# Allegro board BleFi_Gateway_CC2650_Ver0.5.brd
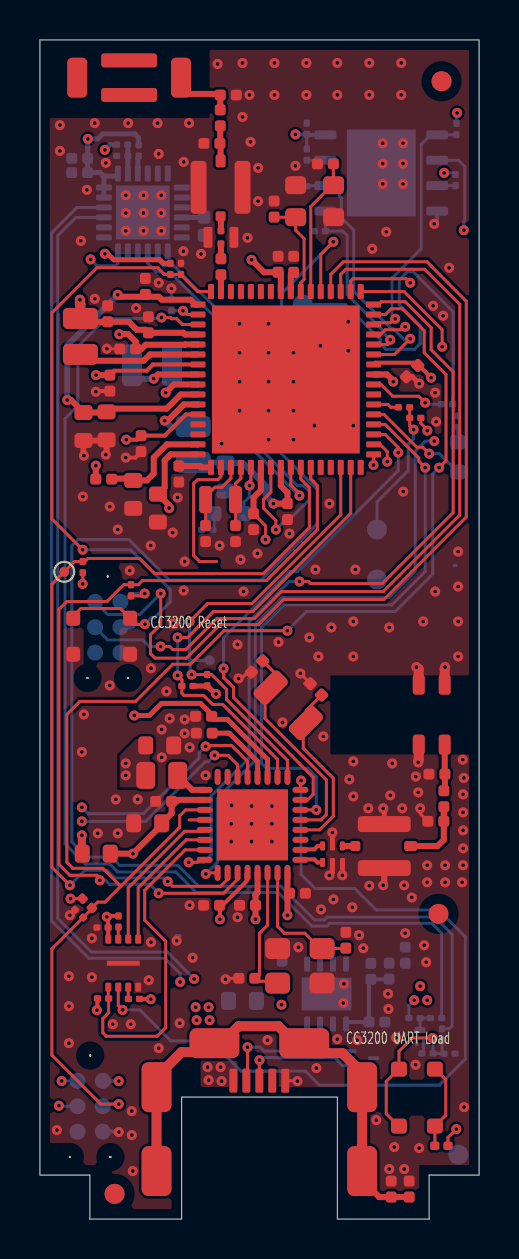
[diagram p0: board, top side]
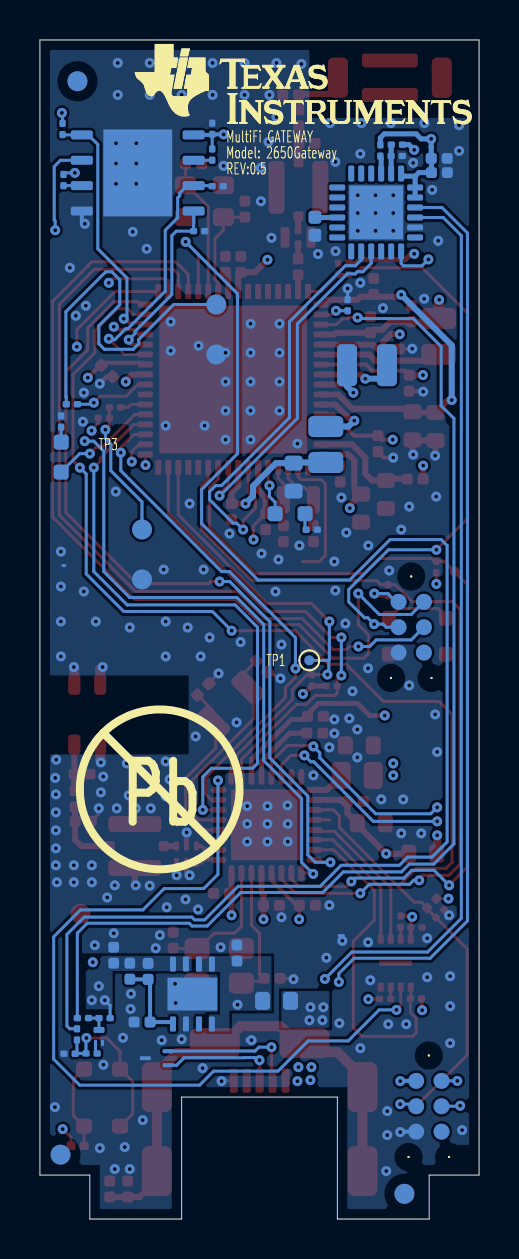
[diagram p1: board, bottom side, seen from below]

Outline 22 x 59 mm; copper layers: TOP, LAYER2, LAYER3, BOTTOM. Coordinates in mm from the lower left corner of the outline.
Outline path: 0,59 0,2.2 2.5,2.2 2.5,0 7.1,0 7.1,6.1 14.9,6.1 14.9,0 19.5,0 19.5,2.2 22,2.2 22,59 0,59

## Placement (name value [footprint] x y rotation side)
A1  ANTENNA_2450AT42B100  [ANTENNA_2450AT42B100N]  7.07 57.11 180 top
A3  2450AT18D0100  [ANTENNA_2450AT18D0100N]  20.28 23.74 90 top
ANT1  1pF  [CAPC1005X60L]  9.03 54.7 90 top
ANT2  22nH  [INDC1005X60L]  8.22 53.82 0 top
ANT3  DNM  [RESC1005X40L]  9.04 56.25 0 top
C15  DNM  [CAPC1005X60L]  20.29 22.26 180 top
C25  DNM  [CAPC1005X60L]  10.77 12.05 180 top
C26  1uF  [CAPC1005X60L]  8.63 24.31 180 top
C27  DNM  [CAPC1005X60L]  15.33 13.55 90 top
C35  100nF  [CAPC0603X35L]  2.16 15.09 135 top
C36  12pF  [CAPC1005X60L]  11.16 27.93 225 top
C38  12pF  [CAPC1005X60L]  14.11 26.22 135 top
C40  DNM  [CAPC1005X60L]  20.23 19.9 180 top
C99  10uF  [CAPC1005X60L]  12.13 12.91 90 bottom
C101  100nF  [CAPC1005X60L]  18.93 42.71 225 top
C111  100nF  [CAPC1005X60L]  8.6 25.16 180 top
C191  100nF  [CAPC1005X60L]  6.6 20.9 180 top
C192  10uF  [CAPC1608X90N]  6.1 19.8 180 top
C221  6.2pF  [CAPC1005X60L]  14.7 52.8 180 top
C231  6.2pF  [CAPC1005X60L]  11.73 50.94 270 top
C241  100nF  [CAPC1005X60L]  12.71 47.38 90 top
C251  100nF  [CAPC1005X60L]  11.93 47.38 90 top
C271  100nF  [CAPC1005X60L]  9 15.7 180 top
C281  100nF  [CAPC1005X60L]  10.8 15.7 180 top
C311  10pF  [CAPC1005X60L]  9.07 47.25 90 top
C321  100nF  [CAPC1005X60L]  12.5 16.3 0 top
C322  100nF  [CAPC0603X35L]  7.07 47.83 270 top
C331  1uF  [CAPC1005X60L]  5.28 46.27 90 top
C361  100nF  [CAPC1005X60L]  5.43 44.35 90 top
C371  4.7uF  [CAPC1005X60N]  4.8 43.54 180 top
C382  100nF  [CAPC1005X60L]  3.39 44.9 90 top
C391  4.7uF  [CAPC1005X60N]  3.5 42.23 270 top
C421  22uF  [CAPC1608X90L]  3.34 40.39 270 top
C422  22uF  [CAPC1608X90L]  2.18 40.36 270 top
C432  10uF  [CAPC1608X90L]  9.29 36.43 90 bottom
C441  4.7uF  [CAPC1005X60N]  5.07 39.2 270 top
C471  10uF  [CAPC1608X90L]  4.67 36.96 270 top
C481  10uF  [CAPC1608X90L]  5.91 36.28 270 top
C491  100nF  [CAPC1005X60L]  6.96 37.68 270 top
C511  22pF  [CAPC1005X60L]  8.3 34.7 270 top
C521  22pF  [CAPC1005X60L]  9.8 34.7 270 top
C541  100nF  [CAPC1005X60L]  10.7 35.3 270 top
C561  100nF  [CAPC1005X60L]  12.4 35.8 270 top
C562  4.7uF  [CAPC1005X60L]  18.5 1.1 90 top
C563  15pF  [CAPC1005X60L]  17.49 12.8 270 bottom
C564  10uF  [CAPC1005X60L]  18.3 12.8 90 bottom
C565  10uF  [CAPC1005X60L]  2.39 52.36 180 bottom
C566  10uF  [CAPC1005X60L]  2.4 53.07 180 bottom
C567  4.7uF  [CAPC1005X60N#2]  8.23 50.13 270 bottom
C568  100nF  [CAPC0603X35L]  13.37 54.27 90 bottom
C574  10uF  [CAPC1608X90N]  5.3 23.7 0 top
C576  100nF  [CAPC0603X35L]  3.42 14.59 180 top
CR1  LS L296-P2Q2-1  [LEDC1708X67L]  20.93 38.88 270 bottom
CR2  LPL296-J2L2-25  [LEDC1707X65L]  8.72 35.29 0 bottom
CR4  DIODE_TPD2EUSB30DR_V1  [SOTFL35P100X50-3M]  15.58 7.7 90 bottom
FIDU8  FIDU_1MM  [FID100X115]  19.97 15.27 0 top
FIDU11  FIDU_1MM  [FID100X115]  3.74 1.26 0 top
FIDU12  FIDU_1MM  [FID100X115]  20.12 56.93 0 top
FIDU13  FIDU_1MM  [FID100X115]  20.97 3.22 180 bottom
FIDU14  FIDU_1MM  [FID100X115]  20.12 56.93 180 bottom
FIDU15  FIDU_1MM  [FID100X115]  3.74 1.26 180 bottom
FL1  DEA202450BT-1294C1  [FIL_DEA202450BT-1294C1N]  9.07 48.8 0 top
FL2  LFB182G  [FIL_LFB182G45BG2D280N]  15.16 18.67 180 top
FL3  BLM18HE152SN1  [FIL_BLM18HE152SN1DL]  3.52 18.28 180 top
J1  MS-156HF  [HIROSE_MS156HFL]  9.05 52.95 270 top
J2  MS-156HF  [HIROSE_MS156HFL]  18.58 18.66 180 top
J3  47491-0001  [MOLEX_474910001L]  9.69 6.92 270 top
L381  2.2uH  [INDC2016X100L]  2.03 43.27 90 top
L401  1uH  [INDC2520X120L]  4.61 42.73 0 bottom
L431  2.2uH  [INDC2016X100L]  7.68 39.66 270 bottom
L474  CIM10U800N  [INDC1608X100L]  9.45 10.92 0 bottom
L475  10uH  [INDC2012X150L]  6.9 22.2 180 top
NOREF  -  []  2.5 0.71 0 top
NOREF#2  -  []  19.5 1.57 0 top
NOREF#3  -  []  18.94 0 90 top
NOREF#4  -  []  4.26 0 90 top
NOREF#5  -  []  0 56.79 0 top
NOREF#6  -  []  0 3.11 0 top
P4  TC2030-CTX-NL  [TAGCONNECT_TC2030-CTX-NLN]  3.15 6.91 270 bottom
P5  TC2030-CTX-NL  [TAGCONNECT_TC2030-CTX-NLN]  4.03 30.88 270 bottom
Q1  CSD13381F4  [DFN100X60X35-3A2N]  19.21 8.81 180 bottom
R10  270  [RESC0603X35L]  20.94 40.19 270 bottom
R12  0  [RESC1005X40L]  20.24 21.43 270 top
R21  270  [RESC0603X35L]  20.68 40.77 180 bottom
R22  270  [RESC0603X35L]  18.52 40.62 180 top
R24  270  [RESC0603X35L]  8.1 34.49 0 bottom
R25  100k  [RESC0603X35L]  12.82 51.68 0 bottom
R26  100k  [RESC0603X35N]  2.6 15.57 135 top
R55  30.1k  [RESC1005X40L]  17.28 9.86 180 bottom
R56  51k  [RESC1005X40L]  16.58 11.99 90 bottom
R61  10k  [RESC0603X35L]  18.52 40.09 0 top
R321  10k  [RESC0603X35L]  6.53 47.26 90 top
R329  10k  [RESC0603X35L]  4.56 31.74 270 top
R330  10k  [RESC0603X35L]  2.15 32.9 270 top
R331  10k  [RESC0603X35L]  8.38 27.24 270 top
R332  10k  [RESC0603X35L]  7.11 26.67 0 top
R333  1Meg  [RESC1005X40L]  17.6 1.9 270 top
R337  270  [RESC0603X35L]  3.84 53.76 0 bottom
R338  270  [RESC0603X35L]  4.41 53.2 180 bottom
R339  4.7k  [RESC0603X35L]  4.95 53.75 270 bottom
R341  100k  [RESC0603X35L]  6.58 46.01 270 bottom
R472  0  [RESC1005X40L]  2.8 37.03 0 top
R532  10k  [RESC0603X35L]  13.37 52.98 90 bottom
R533  10k  [RESC0603X35L]  20.82 51.71 90 bottom
R534  10k  [RESC0603X35L]  13.74 49.43 0 bottom
R535  100k  [RESC0603X35L]  20.87 54.27 90 bottom
R537  10k  [RESC0603X35L]  3.94 14.61 90 top
R538  10k  [RESC0603X35L]  4.43 11.01 0 top
R541  100k  [RESC0603X35L]  3.44 11.04 180 top
R548  10k  [RESC0603X35L]  19.04 10.05 180 bottom
R549  2.7k  [RESC0603X35L]  20.8 8.27 180 bottom
R550  0  [RESC0603X35AN]  20.13 10.06 180 bottom
R551  0  [RESC0603X35AN]  20.14 8.96 90 bottom
R552  0  [RESC0603X35AN]  19.69 8.28 180 bottom
R553  100  [RESC0603X35N]  19.78 3.66 0 top
SW1  BUTTON_CARBON  [SWITCH_TEXAS]  13.17 45.76 90 bottom
SW2  BUTTON_CARBON  [SWITCH_TEXAS]  16.89 34.5 90 bottom
SW3  TL3700AF160Q  [SW_TL3700AF160Q_A2N]  19.79 4.65 90 top
SW4  TL3700AF160Q  [SW_TL3700AF160Q_A2L]  1.67 28.26 0 top
TP1  20_SMD  [TP50]  8.51 27.96 180 bottom
TP2  20_SMD  [TP50]  1.22 32.39 0 top
U1  CC3200R1M2RGC  [QFNFC50P900X900X100-65FL]  16.72 38.26 90 top
U2  CC26xx-5x5  [QFNFC50P500X500X100-33AL]  13.05 17.97 90 top
U3  W25X80ALZPIG  [SON127P600X500X80-9N]  19.9 54.25 270 bottom
U4  W25X20CLUXIG  [SON50P300X200X60-9L]  3.42 11.6 0 top
U5  IC_PERIPH_CP2105_QFN24_V1  [QFNFC50P400X400X80-25BM]  3.2 49.12 90 bottom
U7  TPS79601DR  [SON65P300X300X100-9AL]  13.39 12.76 0 bottom
UNK#REFDES  -  []  16.25 58.8 180 bottom
UNK#REFDES#2  -  [unnamed#2]  20 17.5 180 bottom
Y1  32.768kHz  [XTAL_FC-135L]  13.33 24.82 135 top
Y2  24MHz  [OSCCC250X320X60-4L]  14.14 13.54 180 top
Y3  40MHz  [OSCCC200X250X90-4AL]  12.81 50.13 0 top
Y4  32.768kHz  [XTAL_FC12ML]  9.8 36 180 top

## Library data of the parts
A1 = ANTENNA_2450AT42B100
A3 = ANTENNA_CERAMIC_1_3_GND: User Part Number: #PN; alternate symbols: (ANTENNA_2450AT18D0100L,ANTENNA_2450AT18D0100M)
ANT1 C15 C25-C27 C36 C38 C40 C99 C101 C111 C191 C221 C231 C241 C251 C271 C281 C311 C321 C331 C361 C371 C382 C391 C441 C491 C511 C521 C541 C561-C566 = CAPACITOR: alternate symbols: (CAPC1005X60L,CAPC1005X60M)
ANT2 = INDUCTOR: alternate symbols: (INDC1005X60M,INDC1005X60L)
ANT3 R55 R56 R333 R472 = RESISTOR: alternate symbols: (RESC1005X40L,RESC1005X40M)
C35 C322 C568 C576 = CAPACITOR: alternate symbols: (CAPC0603X35L,CAPC0603X35M)
C192 C421 C422 C432 C471 C481 C574 = CAPACITOR: alternate symbols: (CAPC1608X90L,CAPC1608X90M)
C567 = CAPACITOR: User Part Number: #PN; alternate symbols: (CAPC1005X60L,CAPC1005X60M)
CR1 = LED: alternate symbols: (LEDC1708X67L,LEDC1708X67M)
CR2 = LED: alternate symbols: (LEDC1707X65L,LEDC1707X65M)
CR4 = DIODE_TPD2EUSB30DR_V1: User Part Number: #PN
FIDU8 FIDU11-FIDU15 = FIDMARK
FL1 = FILTER_BPF: User Part Number: #PN
FL2 = FILTER_LFB_0: alternate symbols: (FIL_LFB182G45BG2D280L,FIL_LFB182G45BG2D280M)
FL3 = FILTER_2PIN: alternate symbols: (FIL_BLM18HE152SN1DL,FIL_BLM18HE152SN1DM)
J1 = CONN_COAX_MS-156HF: alternate symbols: (HIROSE_MS156HFAL,HIROSE_MS156HFAM,HIROSE_MS156HFL,HIROSE_MS156HFM)
J2 = CONN_COAX_MS-156HF: alternate symbols: (HIROSE_MS156HFL,HIROSE_MS156HFM)
J3 = CONN_USB_MICRO_5+6_S: User Part Number: #PN; alternate symbols: (MOLEX_474910001L,MOLEX_474910001M)
L381 L431 = INDUCTOR: User Part Number: #PN; alternate symbols: (INDC2016X100L,INDC2016X100M)
L401 = INDUCTOR: alternate symbols: (INDC2520X120L,INDC2520X120M)
L474 = INDUCTOR: alternate symbols: (INDC1608X100L,INDC1608X100M)
L475 = INDUCTOR: alternate symbols: (INDC2012X150L,INDC2012X150M)
P4 P5 = CONN_IDC_TC2030-CTX-NL: alternate symbols: (TAGCONNECT_TC2030-CTX-NLL,TAGCONNECT_TC2030-CTX-NLM)
Q1 = MOSFET_N_CSD13381F4: User Part Number: #PN
R10 R21 R22 R24-R26 R61 R321 R329-R332 R337-R339 R341 R532-R535 R537 R538 R541 R548 R549 R553 = RESISTOR: alternate symbols: (RESC0603X35L,RESC0603X35M)
R12 = RESISTOR_HOR: alternate symbols: (RESC1005X40L,RESC1005X40M)
R550-R552 = RESISTOR: alternate symbols: (RESC0603X35AL,RESC0603X35AM)
SW1 SW2 = BUTTON_CARBON_2
SW3 SW4 = SWITCH_TACT_V1: User Part Number: #PN; alternate symbols: (SW_TL3700AF160Q_A2L,SW_TL3700AF160Q_A2M)
TP1 TP2 = TEST_POINT
U1 = IC_PROC_CC3200_VQFN64: User Part Number: #PN; alternate symbols: (QFNFC50P900X900X100-65FL,QFNFC50P900X900X100-65FM)
U2 = IC_RF_CC26XX_5x5_QFN32: alternate symbols: (QFNFC50P500X500X100-33AL,QFNFC50P500X500X100-33AM)
U3 = IC_FLASH_W25X80AL_WSON8: alternate symbols: (SON127P600X500X80-9L,SON127P600X500X80-9M)
U4 = IC_FLASH_W25X20CL_USON8: alternate symbols: (SON50P300X200X60-9L,SON50P300X200X60-9M)
U5 = IC_PERIPH_CP2105_QFN24_V1_0
U7 = IC_PM_TPS79601_SON8: alternate symbols: (SON65P300X300X100-9AL,SON65P300X300X100-9AM)
Y1 = CRYSTAL: alternate symbols: (XTAL_FC-135L,XTAL_FC-135M)
Y2 = XTAL_4PIN_S: alternate symbols: (OSCCC250X320X60-4L,OSCCC250X320X60-4M)
Y3 = CRYSTAL_13: alternate symbols: (OSCCC200X250X90-4AL,OSCCC200X250X90-4AM)
Y4 = XTAL: alternate symbols: (XTAL_FC12ML,XTAL_FC12MM)

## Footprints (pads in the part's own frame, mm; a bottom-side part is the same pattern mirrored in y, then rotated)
ANTENNA_2450AT18D0100N
  custom 0.15x0.15 smd: 1(0,0) 2(3,0) 3(3,1.3) 4(0,1.3)
ANTENNA_2450AT42B100N
  custom 0.25x0.25 smd: 1(0,0) 2(5.2,0)
  custom 0.175x0.175 smd: 3(2.6,-0.865) 4(2.6,0.865)
CAPC0603X35L
  custom 0.08x0.08 smd: 1(0,0) 2(0.56,0)
CAPC1005X60L
  custom 0.135x0.135 smd: 1(0,0) 2(0.8,0)
CAPC1005X60N
  custom 0.135x0.135 smd: 1(0,0) 2(0.8,0)
CAPC1005X60N#2
  custom 0.16x0.16 smd: 1(0,0) 2(0.9,0)
CAPC1608X90L
  custom 0.187x0.187 smd: 1(0,0) 2(1.4,0)
CAPC1608X90N
  custom 0.187x0.187 smd: 1(0,0) 2(1.4,0)
DFN100X60X35-3A2N
  custom 0.037x0.037 smd: 1(0,0) 2(0.35,0)
  custom 0.075x0.075 smd: 3(0.175,0.65)
FID100X115
  round 1 smd: 1(0,0)
FIL_BLM18HE152SN1DL
  custom 0.187x0.187 smd: 1(0,0) 2(1.4,0)
FIL_DEA202450BT-1294C1N
  custom 0.088x0.088 smd: 1(0,0) 3(0,0.65)
  custom 0.113x0.113 smd: 2(-0.65,0.325) 4(0.65,0.325)
FIL_LFB182G45BG2D280N
  custom 0.062x0.062 smd: 1(0,0) 2(0.5,0) 3(1,0) 4(1,0.825) 5(0.5,0.825) 6(0,0.825)
HIROSE_MS156HFL
  custom 0.125x0.125 smd: 1(0,0) 2(2.775,0)
  custom 0.2x0.2 smd: 3(1.325,-1.1) 4(1.325,1.1)
INDC1005X60L
  custom 0.135x0.135 smd: 1(0,0) 2(0.8,0)
INDC1608X100L
  custom 0.187x0.187 smd: 1(0,0) 2(1.4,0)
INDC2012X150L
  custom 0.237x0.237 smd: 1(0,0) 2(1.6,0)
INDC2016X100L
  custom 0.263x0.263 smd: 1(0,0) 2(1.8,0)
INDC2520X120L
  custom 0.25x0.25 smd: 1(0,0) 2(2,0)
LEDC1707X65L
  custom 0.187x0.187 smd: 1(0,0) 2(1.5,0)
LEDC1708X67L
  custom 0.187x0.187 smd: 1(0,0) 2(1.5,0)
MOLEX_474910001L
  custom 0.1x0.1 smd: 1(0,0) 2(0,0.65) 3(0,1.3) 4(0,1.95) 5(0,2.6)
  custom 0.375x0.375 smd: 6(4.525,-3.85) 7(0.325,-3.85) 8(-1.875,-0.95) 9(-1.875,3.55) 10(0.325,6.45) 11(4.525,6.45)
OSCCC200X250X90-4AL
  custom 0.225x0.225 smd: 1(0,0) 2(1.9,0) 3(1.9,1.6) 4(0,1.6)
OSCCC250X320X60-4L
  custom 0.263x0.263 smd: 1(0,0) 2(2.23,0) 3(2.23,1.73) 4(0,1.73)
QFNFC50P400X400X80-25BM
  custom 0.075x0.075 smd: 1(0,0) 2(0.5,0) 3(1,0) 4(1.5,0) 5(2,0) 6(2.5,0) 7(3.2,0.7) 8(3.2,1.2) 9(3.2,1.7) 10(3.2,2.2) 11(3.2,2.7) 12(3.2,3.2) 13(2.5,3.9) 14(2,3.9) 15(1.5,3.9) 16(1,3.9) 17(0.5,3.9) 18(0,3.9) 19(-0.7,3.2) 20(-0.7,2.7) 21(-0.7,2.2) 22(-0.7,1.7) 23(-0.7,1.2) 24(-0.7,0.7)
  rect 2.7x2.7 smd: 25(1.25,1.95)
QFNFC50P500X500X100-33AL
  oval 0.3x0.8 smd: 1(0,0) 2(0.5,0) 3(1,0) 4(1.5,0) 5(2,0) 6(2.5,0) 7(3,0) 8(3.5,0) 17(3.5,4.8) 18(3,4.8) 19(2.5,4.8) 20(2,4.8) 21(1.5,4.8) 22(1,4.8) 23(0.5,4.8) 24(0,4.8)
  oval 0.8x0.3 smd: 9(4.15,0.65) 10(4.15,1.15) 11(4.15,1.65) 12(4.15,2.15) 13(4.15,2.65) 14(4.15,3.15) 15(4.15,3.65) 16(4.15,4.15) 25(-0.65,4.15) 26(-0.65,3.65) 27(-0.65,3.15) 28(-0.65,2.65) 29(-0.65,2.15) 30(-0.65,1.65) 31(-0.65,1.15) 32(-0.65,0.65)
  rect 3.55x3.55 smd: 33(1.75,2.4)
QFNFC50P900X900X100-65FL
  custom 0.075x0.075 smd: 1(0,0) 2(0.5,0) 3(1,0) 4(1.5,0) 5(2,0) 6(2.5,0) 7(3,0) 8(3.5,0) 9(4,0) 10(4.5,0) 11(5,0) 12(5.5,0) 13(6,0) 14(6.5,0) 15(7,0) 16(7.5,0) 17(8.15,0.65) 18(8.15,1.15) 19(8.15,1.65) 20(8.15,2.15) 21(8.15,2.65) 22(8.15,3.15) 23(8.15,3.65) 24(8.15,4.15) 25(8.15,4.65) 26(8.15,5.15) 27(8.15,5.65) 28(8.15,6.15) 29(8.15,6.65) 30(8.15,7.15) 31(8.15,7.65) 32(8.15,8.15) 33(7.5,8.8) 34(7,8.8) 35(6.5,8.8) 36(6,8.8) 37(5.5,8.8) 38(5,8.8) 39(4.5,8.8) 40(4,8.8) 41(3.5,8.8) 42(3,8.8) 43(2.5,8.8) 44(2,8.8) 45(1.5,8.8) 46(1,8.8) 47(0.5,8.8) 48(0,8.8) 49(-0.65,8.15) 50(-0.65,7.65) 51(-0.65,7.15) 52(-0.65,6.65) 53(-0.65,6.15) 54(-0.65,5.65) 55(-0.65,5.15) 56(-0.65,4.65) 57(-0.65,4.15) 58(-0.65,3.65) 59(-0.65,3.15) 60(-0.65,2.65) 61(-0.65,2.15) 62(-0.65,1.65) 63(-0.65,1.15) 64(-0.65,0.65)
  rect 7.4x7.4 smd: 65(3.75,4.4)
RESC0603X35AN
  custom 0.08x0.08 smd: 1(0,0) 2(0.56,0)
RESC0603X35L
  custom 0.08x0.08 smd: 1(0,0) 2(0.56,0)
RESC0603X35N
  custom 0.105x0.105 smd: 1(0,0) 2(0.66,0)
RESC1005X40L
  custom 0.135x0.135 smd: 1(0,0) 2(0.8,0)
SON50P300X200X60-9L
  custom 0.075x0.075 smd: 1(0,0) 2(0.5,0) 3(1,0) 4(1.5,0) 5(1.5,2.4) 6(1,2.4) 7(0.5,2.4) 8(0,2.4)
  rect 1.651x0.249 smd: 9(0.75,1.2)
SON65P300X300X100-9AL
  custom 0.075x0.075 smd: 1(0,0) 2(0.65,0) 3(1.3,0) 4(1.95,0) 5(1.95,3) 6(1.3,3) 7(0.65,3) 8(0,3)
  rect 2.5x1.65 smd: 9(0.975,1.5)
SON127P600X500X80-9N
  custom 0.113x0.113 smd: 1(0,0) 2(1.27,0) 3(2.54,0) 4(3.81,0) 5(3.81,5.6) 6(2.54,5.6) 7(1.27,5.6) 8(0,5.6)
  rect 4.35x3.45 smd: 9(1.905,2.8)
SOTFL35P100X50-3M
  custom 0.05x0.05 smd: 1(0,0) 2(0.7,0) 3(0.35,1.14)
SW_TL3700AF160Q_A2L
  custom 0.175x0.175 smd: 1(0,0) 2(2.85,0) 3(0,1.8) 4(2.85,1.8)
SW_TL3700AF160Q_A2N
  custom 0.187x0.187 smd: 1(0,0) 2(2.85,0) 3(0,1.8) 4(2.85,1.8)
SWITCH_TEXAS
  round 1 smd: 1(0,0) 2(-2.5,0)
TAGCONNECT_TC2030-CTX-NLN
  round 0.1 hole 1 unplated: (-1.27,0.635) (3.81,-0.381) (3.81,1.651)
  round 0.8 smd: 1(0,0) 2(0,1.27) 3(1.27,0) 4(1.27,1.27) 5(2.54,0) 6(2.54,1.27)
TP50
  round 0.5 smd: 1(0,0)
unnamed#2
  oval 0.025x0.051 smd: 1(4,4)
XTAL_FC12ML
  custom 0.163x0.163 smd: 1(0,0) 2(1.5,0)
XTAL_FC-135L
  custom 0.237x0.237 smd: 1(0,0) 2(2.5,0)

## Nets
GND: A3.2(GND#2) A3.3(GND#3) A3.4(GND#4) ANT2.1 ANT3.2 C15.2 C25.2 C26.2 C27.2 C35.2 C36.2 C38.2 C40.2 C99.2 C101.2 C111.2 C191.2 C192.2 C221.2 C231.1 C241.2 C251.2 C271.2 C281.2 C321.2 C322.1 C331.2 C361.2 C371.2 C382.2 C391.2 C421.2 C422.2 C432.1 C441.2 C471.2 C481.2 C491.2 C511.2 C521.2 C541.2 C561.2 C562.2 C564.2 C565.2 C566.2 C567.2 C568.2 C574.2 C576.2 CR4.3(GND) FL1.2(GND#2) FL1.4(GND#4) FL2.2(GND) FL2.5(GND#5) FL2.6(GND#6) J1.3 J1.4 J2.3 J2.4 J3.5(GND#5) P4.5(GND) P5.5(GND) Q1.2(S) R10.1 R24.1 R25.1 R55.1 R333.1 R338.2 R341.1 R534.1 R549.1 SW1.2 SW2.2 SW4.1 SW4.2 U1.65(EGP) U2.33(VSS) U3.4(GND) U3.9(EGP) U4.4(GND) U4.9(EGP) U5.2(GND) U5.25(EGP) U7.6(GND) U7.9(GND/TAB) Y2.2 Y2.4 Y3.2 Y3.4
VDD: C101.1 C371.1 C391.1 C441.1 C541.1 C563.1 C564.1 C565.1 C566.1 C568.1 C576.1 FL3.2 P4.1(VDD) P5.1(VDD) R26.2 R56.2 R61.2 R321.2 R329.2 R330.2 R331.2 R332.2 R339.1 R472.1 R532.2 R533.2 R535.2 R537.2 R538.2 R541.2 R548.2 R553.2 U1.10(VIN_IO1) U1.37(VIN_DCDC_ANA) U1.39(VIN_DCDC_PA) U1.44(VIN_DCDC_DIG) U1.54(VIN_IO2) U3.8(VCC) U4.8(VCC) U5.5(VIO) U5.6(VDD) U5.7(REGIN) U7.3(OUT#3) U7.4(OUT#4)
VDD_IN: C99.1 L474.2 R337.1 U7.1(IN#1) U7.2(IN#2) U7.8(EN)
VDDR: C281.1 C321.1 C574.1 L475.2 U2.29(VDDR#29) U2.32(VDDR#32)
VDDS: C111.1 C191.1 C192.1 C271.1 FL3.1 U2.11(VDDS2) U2.18(VDDS_DCDC) U2.28(VDDS)
CC2650 BUTTON: R21.2 U1.8(GPIO_17)
CC2650 JTAG_TCK: P4.4(TCK) U2.14(JTAG_TCKC)
CC2650 JTAG_TMS: P4.2(TMS) U2.13(JTAG_TMSC)
CC2650 LED: CR2.2(A) U1.53(GPIO_30)
CC2650 MISO: U2.8(DIO_2) U4.2(DO/IO1)
CC2650 MOSI: U2.22(DIO_9) U4.5(DI/IO0)
CC2650 SCLK: U2.21(DIO_8) U4.6(CLK)
CC3200 BUTTON: R22.2 U1.6(GPIO_15)
CC3200 JTAG_TCK: P5.4(TCK) U1.19(TCK)
CC3200 JTAG_TMS: P5.2(TMS) U1.20(TMS)
CC3200 LED: CR1.2(A) U1.5(GPIO_14)
COEX0: U1.16(TDI) U2.24(DIO_11)
COEX1: U1.17(TDO) U2.25(DIO_12)
COEX2: R330.1 TP2.1 U1.58(GPIO_3) U2.26(DIO_13)
COEX3: R329.1 U1.59(GPIO_4) U2.27(DIO_14)
D+: CR4.1(D+) J3.3(D+) U5.3(D+)
D-: CR4.2(D-) J3.2(D-) U5.4(D-)
DCDC_SW: L475.1 U2.17(DCDC_SW)
FLASH CS: R541.1 U2.23(DIO_10) U4.1(NCS)
HS1: R331.1 TP1.1 U1.62(GPIO_7) U2.9(DIO_3)
HS2: R332.1 U1.63(GPIO_8) U2.10(DIO_4)
I2C SCL: U1.1(GPIO_10)
I2C SDA: U1.2(GPIO_11)
NRESET CC2650: C35.1 P4.3(NRST) R26.1 U1.15(GPIO_22) U2.19(RESET_N)
NRESET CC3200: C322.2 P5.3(NRST) R321.1 SW4.3 SW4.4 U1.32(NRESET)
SOP0: R550.1 U1.35(SOP0)
SOP2: R551.2 U1.21(SOP2)
SSPI_CLK: R25.2 U1.11(FLASH_SPI_CLK) U3.6(CLK)
SSPI_CS: R535.1 U1.14(FLASH_SPI_CS) U3.1(NCS)
SSPI_MISO: U1.13(FLASH_SPI_DIN) U3.2(DO)
SSPI_MOSI: R534.2 U1.12(FLASH_SPI_DOUT) U3.5(DIO)
U16 RESET: U1.18(GPIO_28)
UART RX: U1.4(GPIO_13) U2.6(DIO_0)
UART TX: U1.3(GPIO_12) U2.7(DIO_1)
UARTFL RX: U1.57(GPIO_2) U5.21(TXD_SCI)
UARTFL TX: U1.55(GPIO_1) U5.20(RXD_SCI)
N618375: CR1.1(C) R10.2
N618511: R21.1 SW1.1
N618515: R22.1 R61.1 SW2.1
N622814: CR2.1(C) R24.2
N631122: A3.1(FEEDING POINT) C15.1 R12.1
N631156: C40.1 J2.1 R12.2
N631258: C38.1 U2.4(X32K_Q1) Y1.1
N631262: C36.1 U2.5(X32K_Q2) Y1.2
N632758: FL2.4(BP2) U2.1(RF_P)
N632762: FL2.1(UBP) J2.2
N632770: FL2.3(BP1) U2.2(RF_N)
N632870: C26.1 U2.12(DCOUPL)
N632938: C27.1 U2.31(X24M_P) Y2.1
N632966: C25.1 U2.30(X24M_N) Y2.3
N638264: R549.2 R551.1 R552.1 SW3.3 SW3.4
N638912: C563.2 R55.2 R56.1 U7.5(FB)
N639461: C562.1 J3.6(GND#6) J3.7(GND#7) J3.8(GND#8) J3.9(GND#9) J3.10(GND#10) J3.11(GND#11) R333.2
N742795: R337.2 R338.1 U5.8(VBUS)
N744104: R339.2 U5.9(NRST)
N744832: C567.1 U5.16(NC/DCD_ECI/VPP)
N759449: C471.1 R472.2 U1.47(VDD_ANA2)
N759557: C251.1 C361.1 C382.1 C481.1 L381.2 U1.25(LDO_IN2) U1.36(LDO_IN1) U1.48(VDD_ANA1)
N759727: C331.1 C421.1 C422.1 U1.33(VDD_PA_IN) U1.42(DCDC_PA_OUT)
N759853: C311.1 U1.31(RF_BG)
N759877: C231.2 U1.23(WLAN_XTAL_P) Y3.1
N759881: C221.1 U1.22(WLAN_XTAL_N) Y3.3
N759929: C521.1 U1.52(RTC_XTAL_N) Y4.1
N760199: C511.1 U1.51(RTC_XTAL_P) Y4.2
N760665: R341.2 U1.34(SOP1)
N760769: L401.1 U1.40(DCDC_PA_SW_P)
N760773: L401.2 U1.41(DCDC_PA_SW_N)
N760777: C241.1 U1.24(VDD_PLL)
N760781: C491.1 U1.49(VDD_RAM)
N760789: L431.1 U1.43(DCDC_DIG_SW)
N760837: C432.2 C561.1 L431.2 U1.9(VDD_DIG1) U1.56(VDD_DIG2)
N761005: L381.1 U1.38(DCDC_ANA_SW)
N761145: A1.1(FEED POINT) ANT1.2 ANT3.1
N761299: C311.2 FL1.1(IN)
N761303: FL1.3(OUT) J1.2
N761307: ANT1.1 ANT2.2 J1.1
N764692: R532.1 U3.7(NHOLD)
N764700: R533.1 U3.3(NWP)
N804286: J3.1(VBUS) L474.1
N881760: R537.1 U4.7(NHOLD)
N881768: R538.1 U4.3(NWP)
N913675: R553.1 SW3.1 SW3.2
N916681: Q1.3(D) R548.1 R550.2
N924850: Q1.1(G) R552.2

Pads without a net: A1 2 3 4; FIDU8 1; FIDU11 1; FIDU12 1; FIDU13 1; FIDU14 1; FIDU15 1; J3 4; P4 6; P5 6; U1 7 26 27 28 29 30 45 46 50 60 61 64; U2 3 15 16 20; U5 1 10 11 12 13 14 15 17 18 19 22 23 24; U7 7; UNK#REFDES#2 1

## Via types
v1: diameter 0.5, hole 0.2, TOP to BOTTOM, 334 vias

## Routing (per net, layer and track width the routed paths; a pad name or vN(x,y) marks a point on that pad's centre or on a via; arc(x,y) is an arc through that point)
GND: length 19.1
  TOP w0.15: 13.98,15.47 13.99,15.49 v1(14.08,15.49) ; 7.25,32.85 v1(7.25,32.9) ; 7.04,36.1 v1(6.9,36.1) ; C25.2 9.4,12.05 9.35,12 v1(9.3,12) ; v1(9.95,27.05) 10.1,27.05 10.3,27.25 10.48,27.25 C36.2 ; v1(12.9,6.9) 12.77,6.9 12.75,6.92 J3.5 ; v1(13.05,27.3) 13.55,26.8 13.55,26.79 ; 13.55,26.79 C38.2 13.55,26.79 ; 13.55,26.79 13.26,26.79 ; C371.2 3.36,43.54 v1(3.35,43.55) ; 15.84,14.35 v1(15.99,14.2) ; C40.2 19.05,20.29 v1(19.05,20.55)
  TOP w0.2: v1(4.3,38.1) 4.78,38.1 4.98,38.3 C441.2 ; C391.2 2.83,41.43 v1(2.8,41.4)
  TOP w0.25: FL2.2 14.66,19.33 v1(14.65,19.34) ; v1(15.15,17.2) 15.16,17.21 FL2.6 ; v1(19,41.8) 18.65,42.15 18.36,42.15 ; FL2.5 14.66,17.36 v1(14.5,17.2) ; v1(17.2,20.55) 17.25,20.5 J2.3
  TOP w0.3: v1(17.2,16.7) 17.25,16.75 J2.4 ; v1(2.2,38.2) 2.18,38.22 C422.2 3.31,38.96 C421.2 3.34,38.29 v1(3.3,38.25) ; 6.12,34.87 C481.2 ; v1(6.9,36.1) 6.96,36.16
  TOP w0.5: 18.95,27.55 18.98,27.52 A3.3 ; 20.3,27.55 20.28,27.53 A3.2 ; 18.95,22.95 18.98,22.98 A3.4
  BOTTOM w0.15: R341.1 v1(6.58,46.57) ; 20.85,32.7 20.75,32.7 ; 7.02,14.18 6.8,14.18
  BOTTOM w0.2: v1(3.95,4.35) 3.88,4.35 3.85,4.37 P4.5 ; U3.4 19.9,49.95 v1(19.75,49.8)
  BOTTOM w0.3: 11.55,8.95 v1(11.4,8.95)
  vias: v1(0.85,4.45) v1(1,54.74) v1(1,53.45) v1(1.5,15.2) v1(1.45,12.15) v1(1.45,10.65) v1(1.45,8.8) v1(2.05,48.95) v1(2.1,23.38) v1(2.15,36.15) v1(2.2,25.25) v1(2.35,51.5) v1(2.6,14.05) v1(2.6,12.1) v1(2.74,54.84) v1(2.75,46.05) v1(2.9,19.3) v1(3.3,52.85) v1(3.5,35.65) v1(3.5,26.7) v1(3.65,9.75) v1(3.8,21) v1(3.9,34.5) v1(3.9,19.3) v1(4.3,51.23) v1(4.3,50.34) v1(4.3,49.45) v1(4.42,54.84) v1(4.5,32.45) v1(4.55,9.75) v1(4.6,5.4) v1(4.6,4.2) v1(4.65,2.4) v1(4.82,45.58) v1(4.9,21) v1(5.19,51.23) v1(5.19,50.34) v1(5.19,49.45) v1(5.55,33.7) v1(5.45,11.95) v1(5.56,27.56) v1(5.56,13.85) v1(5.89,54.84) v1(5.95,53.3) v1(5.95,46.85) v1(5.95,8.55) v1(6.08,51.23) v1(6.08,50.34) v1(6.08,49.45) v1(6.1,24.5) v1(6.1,23.1) v1(6.34,26.41) v1(6.5,25.05) v1(6.65,34.35) v1(6.7,29.8) v1(6.85,13.93) v1(7,9.8) v1(7.2,52.9) v1(7.19,48.43) v1(7.2,31.45) v1(7.25,25) v1(7.25,24.3) v1(7.47,54.84) v1(7.5,23.6) v1(7.5,15.7) v1(7.65,13.07) v1(8.07,48.29) v1(8.3,22.2) v1(8.9,57.8) v1(9,33.7) v1(9.1,38.8) v1(9.6,20.7) v1(9.59,19.77) v1(9.59,18.88) v1(9.9,28.75) v1(9.9,15.1) v1(10,44.8) v1(10,43.35) v1(10,41.9) v1(10,40.45) v1(10.05,33) v1(10.15,57.85) v1(10.15,55.15) v1(10.2,31.4) v1(10.4,49.1) v1(10.5,56.25) v1(10.55,53.9) v1(10.6,20.66) v1(10.6,19.77) v1(10.6,18.88) v1(10.93,52.6) v1(10.93,50.93) v1(10.9,33.3) v1(11.45,44.8) v1(11.45,43.35) v1(11.45,41.9) v1(11.45,40.45) v1(11.45,39) v1(11.62,20.66) v1(11.62,19.77) v1(11.62,18.88) v1(11.75,57.85) v1(11.75,56.25) v1(11.95,28.87) v1(12.15,24.85) v1(12.5,34.3) v1(12.7,43.35) v1(12.7,41.9) v1(12.7,40.45) v1(12.7,39) v1(12.8,52.7) v1(12.95,13.6) v1(13.35,57.85) v1(13.35,56.25) v1(13.5,29.1) v1(13.75,39.7) v1(13.8,32.5) v1(13.95,28.15) v1(13.85,7.55) v1(14.05,43.7) v1(14.2,24.15) v1(14.5,35.8) v1(14.6,29.6) v1(14.71,15.99) v1(14.9,57.85) v1(14.9,56.25) v1(14.9,9) v1(15.23,11.77) v1(15.2,10.81) v1(15.45,44.9) v1(15.45,43.45) v1(15.5,22) v1(15.65,15.6) v1(15.7,39.7) v1(15.7,29.9) v1(15.7,28.15) v1(15.7,22.9) v1(15.7,21.15) v1(15.8,32.5) v1(15.9,8.95) v1(16.2,13.55) v1(16.5,57.85) v1(16.5,56.25) v1(16.45,20.55) v1(16.5,16.68) v1(16.65,48.55) v1(16.85,4.95) v1(17.17,53.83) v1(17.17,52.82) v1(17.17,51.8) v1(17.35,49.4) v1(17.44,11.27) v1(17.5,29.6) v1(17.55,21.2) v1(17.46,10.51) v1(17.5,2.5) v1(17.65,22.8) v1(17.84,9.07) v1(17.75,3.6) v1(18.1,57.85) v1(18.1,56.25) v1(18.19,53.83) v1(18.19,52.82) v1(18.19,51.8) v1(18.2,36.4) v1(18.15,20.55) v1(18.25,16.7) v1(18.25,2.5) v1(18.3,14.3) v1(18.63,16.09) v1(18.83,22.14) v1(18.82,7.72) v1(18.86,27.62) v1(18.95,22.85) v1(18.95,21.35) v1(19,3.55) v1(19.2,29.9) v1(19.25,13.7) v1(19.35,12.85) v1(19.4,17.7) v1(19.4,16.85) v1(19.7,45.7) v1(19.8,41.35) v1(19.8,31.4) v1(19.85,39.9) v1(20.2,45.2) v1(20.3,27.62) v1(20.3,17.7) v1(20.3,16.85) v1(20.5,47.6) v1(20.95,33.4) v1(20.95,31.65) v1(20.95,29.9) v1(20.95,28.15) v1(21.18,22.99) v1(21.23,22.07) v1(21.2,21.25) v1(21.2,20.35) v1(21.2,19.45) v1(21.2,18.55) v1(21.2,17.7) v1(21.15,16.85) v1(21.25,5.6)
VDD: length 48.9
  TOP w0.15: R541.2 2.88,10.48 ; R329.2 5.13,31.18 v1(5.25,31.3) ; C541.1 10.7,35.3 11.3,34.69 v1(11.3,34) ; v1(20.86,4.5) 20.44,4.08 R553.2 ; v1(19.41,39.45) 19.41,39.49 19.08,39.82 R61.2 ; v1(2.14,31.78) 2.15,31.79 R330.2 ; R26.2 v1(1.53,16.03)
  TOP w0.2: U1.44 7.31,40.26 6.25,39.2 C441.1 4.87,39 v1(4.33,39) ; U4.8 3.42,14.58 C576.1 3.42,15.06 v1(3.35,15.12) 3.39,15.17 R537.2 ; R538.2 5.54,11.01 v1(5.55,11) ; U1.39 5.66,42.76 5.35,42.45 3.72,42.45 C391.1 ; U1.10 16.81,42.85 18.79,42.85 C101.1 18.94,42.76 v1(19.6,42.1) ; R541.2 2.88,10.48 v1(2.85,10.45)
  TOP w0.25: v1(8.82,26.28) 8.79,26.28 R331.2 8.37,26.67 R332.2 ; R321.2 6.18,47.82 6,48 3.7,48 3.4,48.3 v1(3.25,48.3)
  TOP w0.3: v1(2.8,37.7) 2.8,37.7 R472.1 ; U1.37 7.27,43.76 7.26,43.75 5.3,43.75 5.09,43.54 C371.1 4.8,43.9 4.41,44.29 3.99,44.29 v1(3.98,44.27) ; C541.1 10.7,36.1 11.07,36.47 U1.54 ; C391.1 v1(2.81,42.23)
  TOP w0.4: v1(2.1,19.2) 2.1,18.3 FL3.2
  BOTTOM w0.15: v1(20.25,52.35) 20.74,52.35 R533.2 ; R535.2 20.87,55.32 v1(20.9,55.35) ; R532.2 13.37,54.27 ; v1(5.25,31.3) 4.58,31.3 4.17,30.88 P5.1 ; R548.2 18.48,10.05 18.48,10.68 v1(18.75,10.95)
  BOTTOM w0.2: v1(3.95,6.9) 3.8,6.9 3.79,6.91 P4.1 ; v1(12.8,54.27) C568.1 13.39,54.25 U3.8
  BOTTOM w0.25: 3.2,52.18 3.77,52.18 U5.7 ; 3.2,52.18 3.02,52.36 C565.1 2.39,53.07 C566.1 2.4,53.65 2.4,53.65 v1(2.4,54.05) 2.9,54.05 3.15,54.3 4.75,54.3 4.95,54.1 R339.1 ; 3.2,52.18 3.2,52.18 U5.6 U5.5
  vias: v1(19.05,11.65) v1(19.4,10.95)
VDD_IN: length 55.7
  LAYER3 w0.25: v1(3.25,53.5) 2.05,53.5 0.63,52.08 0.63,14.68 2,13.3 7.1,13.3 7.5,13.7 10.8,13.7 12.1,12.4 v1(12.1,10.72)
  BOTTOM w0.25: R337.1 3.51,53.76 v1(3.25,53.5)
VDDR: length 5
  TOP w0.2: 10.8,16.2 10.9,16.3 10.9,16.35
  TOP w0.3: v1(10.8,15) C281.1 10.8,16.25 10.9,16.35 U2.29 ; U2.32 12.4,16.45 ; 12.4,16.45 12.59,16.26 ; 12.4,16.45 12.4,16.4 C321.1 12.4,16.2 v1(12.4,15.2)
  vias: v1(4.3,22.8) v1(4.3,22.2)
VDDS: length 18.4
  TOP w0.2: v1(9.01,15) 9.01,15.57 ; 9.01,15.57 9.01,15.69 C271.1 ; 9.01,15.57 10.35,16.9 10.35,17.27 U2.28
  TOP w0.25: U2.11 11.4,23 9.39,25.01 9.39,25 8.7,25 8.6,25.1 C111.1 8.65,25.2 8.05,25.8 6.09,25.8 5.49,25.2 v1(4.72,25.2)
  TOP w0.3: U2.18 6.93,20.97 6.85,20.9 C191.1 6.6,20.3 C192.1 6.1,19.72 v1(4.66,18.28) FL3.1
CC2650 BUTTON: length 3.8
  TOP w0.15: U1.8 17.09,41.76 17.68,41.17 18.98,41.17 v1(19.3,40.85)
  BOTTOM w0.15: v1(19.3,40.85) 19.38,40.77 R21.2
CC2650 JTAG_TCK: length 26.2
  TOP w0.15: v1(8.75,23.2) 9.43,23.2 9.9,22.73 U2.14
  LAYER2 w0.15: v1(2.1,19.9) 0.95,18.75 0.95,7.8 1.6,7.15 1.6,6.32 v1(0.95,5.67) 0.95,5.65
  BOTTOM w0.15: P4.4 0.98,5.64 v1(0.95,5.67) ; v1(2.1,19.9) 5.3,19.9 8.28,22.88 8.43,22.88 v1(8.75,23.2)
CC2650 JTAG_TMS: length 26.4
  TOP w0.15: v1(8.3,23.65) 8.5,23.65 8.55,23.7 9.6,23.7 10.4,22.9 U2.13
  LAYER2 w0.15: v1(1.09,6.91) 0.6,7.4 0.6,19.1 v1(2.1,20.6)
  BOTTOM w0.15: v1(8.3,23.65) 7.98,23.33 7.98,23.08 5.18,20.28 2.42,20.28 v1(2.1,20.6) ; v1(1.09,6.91) 1.09,6.91 P4.2
CC2650 LED: length 2.5
  TOP w0.15: U1.53 10.57,36.97 10.5,36.9 v1(10.5,36.7)
  BOTTOM w0.15: v1(10.5,36.7) 10.5,36.15 10.22,35.87 10.22,35.29 CR2.2
CC2650 MISO: length 41.3
  TOP w0.15: U2.8 13.05,21.92 v1(13.08,21.95) ; v1(4.14,10.47) 3.92,10.68 U4.2
  BOTTOM w0.15: v1(4.14,10.47) 5,10.47 6.55,8.91 8.56,8.91 10.07,7.4 13.3,7.4 14,6.7 20.01,6.7 21.31,8 21.31,14.12 19.96,15.47 16.84,15.47 15.77,16.53 13.79,16.53 13.08,17.25 v1(13.08,21.95)
CC2650 MOSI: length 6.9
  TOP w0.15: U2.22 7.32,18.97 4.92,16.57 U4.5
CC2650 SCLK: length 7.6
  TOP w0.15: U2.21 8.18,19.4 7.25,19.4 4.42,16.57 U4.6
CC3200 BUTTON: length 1.3
  TOP w0.15: U1.6 17.44,40.76 17.58,40.62 R22.2
CC3200 JTAG_TCK: length 39.7
  TOP w0.15: U1.19 15.07,46.99 15.06,47 15.06,47.27 15.32,47.52 19.28,47.52 21.03,45.77 21.03,35.23 17.2,31.4 12.1,31.4 11.7,31 11.7,31 10.75,30.05 8.87,30.05 7.32,28.5 6.65,28.5 6.5,28.65 v1(6.04,28.65)
  BOTTOM w0.15: P5.4 3.4,28.98 5.15,28.98 5.48,28.65 v1(6.04,28.65)
CC3200 JTAG_TMS: length 45.6
  TOP w0.15: U1.20 14.57,47.27 15.2,47.9 19.4,47.9 19.6,47.7 19.6,47.68 21.36,45.92 21.36,35.13 17.23,31 12.2,31 10.94,29.74 9.02,29.74 7.34,28.07 5.77,28.07 5.54,28.3 5.54,29.23 6.05,29.75 v1(6.05,31.3)
  BOTTOM w0.15: P5.2 3.4,30.25 5,30.25 v1(6.05,31.3)
CC3200 LED: length 5.4
  TOP w0.15: U1.5 17.24,40.26 18.88,38.62 19.18,38.62 v1(19.5,38.3)
  BOTTOM w0.15: v1(19.5,38.3) 20.01,38.3 CR1.2
COEX0: length 40.3
  TOP w0.15: v1(13,31.9) 13.45,31.9 13.55,31.8 17.15,31.8 20.7,35.35 20.7,42.4 19.6,43.5 19.6,44.6 18.3,45.9 17.1,45.9 16.96,45.76 U1.16 ; U2.24 8,17.97 7.88,17.85 v1(7.45,17.85)
  BOTTOM w0.15: v1(7.45,17.85) 8.21,17.85 8.58,18.22 8.58,21.17 10.48,23.07 10.48,29.89 12.49,31.9 v1(13,31.9)
COEX1: length 43.2
  TOP w0.15: U2.25 8.36,17.32 v1(8.31,17.27) ; v1(20.15,43.65) 20.15,44.5 18.24,46.41 U1.17
  LAYER3 w0.15: v1(20.15,43.65) 21.03,43.65 21.4,43.27 21.4,39.52 20.8,38.93 v1(19.76,38.93)
  BOTTOM w0.15: v1(19.76,38.93) 19.3,38.93 18.8,38.42 18.8,32.4 17.5,31.1 12.13,31.1 10.79,29.76 10.79,22.94 8.89,21.04 8.89,17.85 v1(8.31,17.27)
COEX2: length 42.3
  TOP w0.15: v1(6.4,16.89) 6.64,16.65 9.05,16.65 9.4,17 U2.26 ; v1(1.5,16.7) 0.6,17.6 0.6,31.77 TP2.1 1.74,32.9 R330.1 2.25,32.9 2.4,33.05 5,33.05 5.75,32.3 11.2,32.3 13.5,34.6 13.5,36.6 13.07,37.03 U1.58
  BOTTOM w0.15: v1(1.5,16.7) 2.25,17.45 3.37,17.45 3.76,17.06 6.23,17.06 v1(6.4,16.89)
COEX3: length 40.8
  TOP w0.15: v1(3,16.95) 3,17.05 2.85,17.2 1.5,17.2 0.95,17.75 0.95,30.5 1.35,30.9 3.36,30.9 4.2,31.74 R329.1 4.93,31.74 5.13,31.95 11.35,31.95 13.9,34.5 13.9,36.7 13.7,36.9 13.7,36.9 13.57,37.03 U1.59 ; v1(5.95,16.3) 9.2,16.3 9.9,17 U2.27
  BOTTOM w0.15: v1(5.95,16.3) 5.5,16.75 3.48,16.75 3.28,16.95 v1(3,16.95)
D+: length 57.1
  TOP w0.15: J3.3 10.99,7.94 v1(11,7.95)
  LAYER3 w0.15: v1(7.72,12.01) 8.16,11.58 8.92,11.58 9.42,11.08 9.42,9.47 9.8,9.09 10.68,9.09 10.93,8.84 10.93,8.19 11,8.12 v1(11,7.95)
  BOTTOM w0.15: U5.3 1.8,50.12 0.89,49.21 0.89,15.05 2.58,13.36 6.36,13.36 6.37,13.35 6.39,13.35 v1(7.72,12.01) ; v1(11,7.95) 11.12,7.95 11.25,8.08 11.74,8.08 11.75,8.07 14.78,8.07 15.15,7.7 CR4.1
D-: length 58.2
  TOP w0.15: J3.2 10.4,6.98 v1(10.4,8.6)
  LAYER3 w0.15: v1(7.02,11.86) 7.61,11.28 8.74,11.28 9.07,10.95 9.07,9.34 9.81,8.6 v1(10.4,8.6)
  BOTTOM w0.15: CR4.2 15.57,8.41 11.22,8.41 11.03,8.6 v1(10.4,8.6) ; v1(7.02,11.86) 7.02,12.28 6.26,13.05 2.45,13.05 0.58,14.92 0.58,49.34 1.86,50.62 U5.4
DCDC_SW: length 1.7
  TOP w0.3: U2.17 7.63,21.47 L475.1
FLASH CS: length 17
  TOP w0.15: U2.23 7.27,18.47 5.25,16.45 5.25,14.95 6.3,13.9 6.3,9.58 5.87,9.14 3.33,9.14 3.15,9.32 3.15,10.03 3.44,10.32 R541.1 3.42,11.05 U4.1
HS1: length 23.5
  TOP w0.15: U1.62 15.07,35.24 10.63,30.8 8.4,30.8 v1(7.5,29.9) ; U2.9 12.4,22.95 9.35,26 9.35,26.5 8.61,27.24 R331.1 v1(7.6,27.24)
  BOTTOM w0.15: 7.53,27.96 7.53,27.32 v1(7.6,27.24) ; 7.53,27.96 TP1.1 ; 7.53,27.96 7.5,27.98 v1(7.5,29.9)
HS2: length 23.5
  TOP w0.15: v1(6.9,29.1) 7.4,29.1 8.7,30.4 10.66,30.4 15.57,35.31 U1.63 ; U2.10 11.9,23 9.15,25.75 8.65,25.75 8.2,26.2 7.22,26.2 7.11,26.31 R332.1 7.11,26.76 7.12,26.77 7.12,26.98 v1(6.9,27.2)
  BOTTOM w0.15: v1(6.9,29.1) v1(6.9,27.2)
I2C SCL: length 0.5
  TOP w0.15: v1(16.71,37.73) 16.72,37.74 U1.1
I2C SDA: length 1.3
  TOP w0.15: U1.2 17.04,38.76 17.4,38.4 v1(17.4,37.9)
Net_2: length 0.8
  TOP w0.15: 8.25,19.97 7.47,19.97
Net_8: length 6.9
  TOP w0.15: 8.85,32.9 8,32.9 7.7,33.2 7.7,36.8 7.9,37 8.92,37 9.07,37.15 9.07,37.61
Net_13: length 2.1
  BOTTOM w0.15: 3.9,48.42 3.9,47.82 3.79,47.7 2.86,47.7 v1(2.54,48.02)
NRESET CC2650: length 69.3
  TOP w0.15: v1(20,37.6) 20.34,37.95 20.34,42.25 19.25,43.35 19.25,44.45 18.15,45.55 17.6,45.55 17.31,45.26 U1.15 ; 4.05,16.65 3.26,15.86 2.89,15.86 R26.1 2.6,15.52 C35.1 0.6,13.52 0.6,8.2 3.05,5.75 v1(3.95,5.75) ; 4.05,16.65 7,19.6 7,20.17 7.3,20.47 U2.19 ; 4.05,16.65 3.15,17.55 1.65,17.55 1.35,17.85 1.35,25.25 2,25.9 4.79,25.9 6.66,27.76 7.54,27.76 9.22,29.44 v1(12.39,29.44)
  BOTTOM w0.15: v1(12.39,29.44) 13.36,30.4 17.8,30.4 19.68,32.28 19.68,37.28 v1(20,37.6) ; v1(3.95,5.75) 3.26,5.75 P4.3
NRESET CC3200: length 35.6
  TOP w0.15: 7.07,47.27 6.54,47.27 ; 7.07,47.27 7.07,47.25 7.9,46.41 U1.32 ; 7.07,47.27 C322.2 ; 7.07,47.27 6.54,47.27 ; 6.54,47.27 R321.1 6.24,47.26 5.9,47.6 2.85,47.6 0.6,45.35 0.6,35.03 v1(2.14,33.49) ; v1(5.26,29.77) 5.18,29.77 5.16,29.75 4.65,29.75 4.52,29.88 SW4.4 4.52,30.06 4.03,30.55 2.05,30.55 1.67,30.17 SW4.3
  BOTTOM w0.15: v1(2.14,33.49) 4.54,33.49 6.53,31.5 6.53,30.88 5.74,30.09 5.58,30.09 v1(5.26,29.77) 4.81,29.77 4.65,29.61 P5.3
SOP0: length 57
  TOP w0.15: U1.35 7.14,44.76 6.85,45.05 6.6,45.05 6.54,45.11 v1(6.09,45.11)
  BOTTOM w0.15: v1(6.09,45.11) 5.9,45.11 5.85,45.06 3.3,45.06 1.9,43.66 1.9,40.7 1.26,40.06 1.26,18.77 2.27,17.76 3.5,17.76 3.89,17.37 6.8,17.37 7.83,16.34 11.94,16.34 13.62,14.66 14.38,14.66 14.52,14.8 19.63,14.8 20.13,14.3 R550.1
SOP2: length 74.2
  TOP w0.15: U1.21 14.07,48.27 v1(14.7,48.9)
  BOTTOM w0.15: v1(14.7,48.9) 12.1,46.3 12.1,38.3 13.9,36.5 13.9,34.8 11.08,31.98 6.48,31.98 4.46,34 1.9,34 1.6,33.7 1.6,18.87 2.36,18.11 3.58,18.11 3.99,17.7 6.91,17.7 7.96,16.65 12.07,16.65 13.75,14.97 14.25,14.97 14.39,15.11 19.78,15.11 20.65,14.24 20.65,9.66 20.51,9.52 R551.2
SSPI_CLK: length 13
  TOP w0.15: v1(18.55,44.05) 17.76,43.26 U1.11
  BOTTOM w0.15: v1(18.55,44.05) 18.5,44 18.25,44 17.7,44.55 17.6,44.55 15.72,46.43 15.72,49.48 15.1,50.1 15.1,51.1 14.99,51.21 14.99,51.34 14.63,51.71 U3.6 13.4,51.71 13.38,51.68 R25.2
SSPI_CS: length 12.6
  TOP w0.15: U1.14 16.81,44.85 17.55,44.85 17.75,45.05 v1(17.8,45.05)
  BOTTOM w0.15: v1(17.8,45.05) 17.64,45.21 17.64,47.09 19.1,48.55 19.1,53.78 19.58,54.25 U3.1 20.85,54.25 R535.1
SSPI_MISO: length 14.9
  TOP w0.15: U1.13 17.06,44.26 17.3,44.5 18.05,44.5 18.2,44.65 v1(18.3,44.65)
  LAYER3 w0.15: v1(21.23,49.48) 21.23,49.03 21.4,48.86 21.4,44.52 21.05,44.17 19.23,44.17 18.75,44.65 v1(18.3,44.65)
  BOTTOM w0.15: U3.2 20.97,52.98 21.28,52.67 21.28,49.98 21.23,49.93 v1(21.23,49.48)
SSPI_MOSI: length 9.3
  TOP w0.15: v1(17.55,44) 17.55,43.9 17.41,43.76 U1.12
  BOTTOM w0.15: v1(17.55,44) 17.23,44.32 17.23,44.42 15.39,46.26 15.39,49.21 15.17,49.43 R534.2 ; U3.5 14.3,49.65 14.3,49.65 R534.2 ; 14.3,49.44 R534.2
U16 RESET: length 3.6
  TOP w0.15: v1(18.55,46.85) 18.35,47.05 15.68,47.05 15.57,46.94 U1.18
UART RX: length 30.4
  TOP w0.15: U1.4 17.3,39.76 18.98,38.08 18.98,37.92 v1(19.3,37.6) ; v1(13.84,20.47) U2.6
  BOTTOM w0.15: v1(19.3,37.6) 19.3,32.4 17.63,30.73 12.22,30.73 11.1,29.61 11.1,22.8 11.34,22.55 13.41,22.55 13.84,22.13 v1(13.84,20.47)
UART TX: length 25.3
  TOP w0.15: v1(17.95,38.35) 17.95,38.61 17.3,39.26 U1.3 ; v1(9.2,27.55) 9.2,27.1 9.43,26.87 9.43,26.87 9.7,26.6 9.7,26.09 13.69,22.1 13.69,21.25 13.41,20.97 U2.7
  BOTTOM w0.15: v1(17.95,38.35) 17.95,37.45 12.9,32.4 12.5,32.4 9.2,29.1 v1(9.2,27.55)
UARTFL RX: length 17.4
  TOP w0.15: v1(13,36.2) 13,36.3 12.57,36.73 U1.57
  BOTTOM w0.15: v1(13,36.2) 12.97,36.2 9.1,40.07 9.1,44.8 6.6,47.3 6.2,47.3 6.1,47.4 5.82,47.4 5.41,47.82 5.41,48.42 U5.21
UARTFL TX: length 21.9
  TOP w0.15: U1.55 11.57,36.37 11.2,36 11.2,35.57 11.82,34.95 v1(11.82,34.5)
  BOTTOM w0.15: v1(11.82,34.5) 12.14,34.82 12.32,34.82 13.5,36 13.5,36.4 13.2,36.7 12.9,36.7 9.5,40.1 9.5,44.9 6.7,47.7 6.2,47.7 5.9,48 U5.20
N618375: length 0.7
  BOTTOM w0.15: CR1.1 20.93,39.57 R10.2
N618511: length 19
  BOTTOM w0.15: R21.1 20.68,41.14 20.7,41.16 20.7,45.4 18.7,47.4 18.4,47.4 18,47 18,45.75 19.05,44.7 19.05,43.8 18.77,43.52 17.33,43.52 17.05,43.8 17.05,44.01 15.3,45.76 SW1.1
N618515: length 7
  TOP w0.15: R22.1 18.52,40.09 R61.1 18.52,39.7 v1(18.72,39.5)
  BOTTOM w0.15: v1(18.72,39.5) 18.72,39.05 18.45,38.78 18.45,37.45 16.89,35.89 SW2.1
N622814: length 0.8
  BOTTOM w0.15: CR2.1 8.72,34.55 R24.2
N631122: length 2.3
  TOP w0.3: A3.1 20.28,22.27 C15.1 20.29,21.48 R12.1
N631156: length 4.2
  TOP w0.3: C40.1 20.23,18.98 19.92,18.66 J2.1 ; C40.1 20.24,19.91 R12.2 20.23,20.63 C40.1
N631258: length 9.2
  TOP w0.15: U2.4 14.01,19.47 14.7,20.16 14.7,22.05 13.19,23.56 13.19,24.69 Y1.1 13.33,25.38 13.35,25.4 13.35,25.46 C38.1 14.13,26.22 14.25,26.1
N631262: length 11.1
  TOP w0.15: U2.5 14.09,19.97 14.35,20.24 14.35,21.97 11.28,25.04 11.28,26.31 Y1.2 11.59,26.59 12.05,27.05 12.04,27.05 C36.1
N632758: length 1.2
  TOP w0.2: U2.1 13.08,18 13.75,18 13.91,17.84 FL2.4
N632762: length 0.6
  TOP w0.3: J2.2 15.8,18.67 FL2.1
N632770: length 1.2
  TOP w0.2: U2.2 13.08,18.5 13.75,18.5 13.92,18.67 FL2.3
N632870: length 3.6
  TOP w0.25: C26.1 9.41,24.31 9.43,24.3 9.5,24.3 10.9,22.9 U2.12
N632938: length 6.6
  TOP w0.15: U2.31 11.9,14.65 12.25,14.3 13.27,14.3 14.04,13.54 Y2.1 15.26,13.54 C27.1
N632966: length 6.8
  TOP w0.15: Y2.3 11.91,11.81 11.81,11.9 10.9,11.9 10.77,12.03 C25.1 10.8,12.05 11,12.25 11,14.3 11.4,14.7 U2.30
N638264: length 8.4
  TOP w0.15: SW3.3 17.96,4.65 17.35,5.26 17.35,6.89 17.96,7.5 SW3.4 17.99,8.39 18.66,9.06 v1(19.67,9.06)
  BOTTOM w0.15: v1(19.67,9.06) 19.69,9.04 R552.1 20.24,8.28 R549.2 20.14,8.29 R551.1
N638912: length 4.3
  BOTTOM w0.2: C563.2 17.49,11.99 R56.1 16.48,11.89 R55.2 15.43,9.86 U7.5
N639461: length 27.1
  TOP w0.3: 16.14,1.96 17,1.1 R333.2 C562.1
  TOP w0.5: 16.14,2.4 J3.11 16.14,2.4 ; 16.14,2.4 16.14,1.54 16.1,1.5 ; 16.14,2.4 16.14,6.6 ; J3.6 5.84,2.4 5.84,6.6 ; J3.8 8.74,8.8 ; J3.8 8.74,8.8 ; J3.8 9.1,8.8 9.95,9.65 11.95,9.65 12.45,9.15 12.45,8.8 ; 8.74,8.8 9.25,8.52 9.25,8.35 ; 8.74,8.8 8.74,8.79 8.3,8.35 7.09,8.35 5.84,7.1 ; 5.84,6.6 J3.7 5.84,6.6 ; 5.84,6.6 5.84,7.1 ; 16.14,6.6 J3.10 16.14,6.6 ; 16.14,6.6 16.14,7.31 15.15,8.3 13.74,8.3 J3.9 12.45,8.8 ; 5.84,7.1 5.84,7.59 ; 12.45,8.8 12.4,8.8
N742795: length 1.5
  BOTTOM w0.2: R337.2 4.4,53.8
  BOTTOM w0.25: R337.2 4.41,53.75 R338.1 4.41,53.2 4.41,52.32 U5.8
N744104: length 0.9
  BOTTOM w0.25: R339.2 4.95,53.19 4.9,53.08 U5.9
N744832: length 1.1
  BOTTOM w0.25: C567.1 8.17,50.12 U5.16
N759449: length 5.6
  TOP w0.3: R472.2 3.6,37.03 3.62,37.05 4.58,37.05 C471.1 5.36,36.96 5.7,37.3 5.7,38.1 6.36,38.76 U1.47
N759557: length 34.8
  TOP w0.2: L381.2 2.19,44.9
  TOP w0.3: U1.36 7.27,44.26 7.18,44.35 C361.1 5.28,44.5 4.85,44.5 4.45,44.9 C382.1 2.19,44.9 L381.2 ; v1(10.6,48) 11.22,47.38 C251.1 12.07,47.31 U1.25 ; U1.48 6.55,38.26 6.25,37.96 6.25,36.61 C481.1 6.47,35.71 v1(6.47,35.57)
  TOP w0.5: L381.2 2.03,45.77 2,45.8 v1(2,46)
  LAYER3 w0.4: v1(6.47,35.57) 6.25,35.8 6.25,37.44 7.16,38.36 7.16,44.34 7.07,44.43 ; 7.07,44.43 5.15,44.43 4.6,44.98 2.9,44.98 2,45.87 v1(2,46) ; 7.07,44.43 7.07,44.47 v1(10.6,48)
N759727: length 17.8
  TOP w0.3: U1.33 7.79,45.76 7.55,46 6.1,46 5.95,46.15 5.4,46.15 5.28,46.27 C331.1 5.27,46.27 5.15,46.15 4.05,46.15 3.95,46.25 v1(3.9,46.25) ; v1(1.37,40.98) 1.56,40.98 C422.1 3.31,40.36 C421.1 3.5,40.55 6.35,40.55 7.06,41.26 U1.42
  BOTTOM w0.3: v1(3.9,46.25) 1.37,43.72 v1(1.37,40.98)
N759853: length 0.8
  TOP w0.3: U1.31 9.07,47.25 C311.1
N759877: length 5
  TOP w0.15: C231.2 11.74,50.13 Y3.1 12.81,49.48 13.23,49.06 13.23,47.01 13.07,46.85 U1.23
N759881: length 7
  TOP w0.15: C221.1 14.7,51.74 Y3.3 14.64,51.73 13.57,50.66 U1.22 13.6,46.44 13.6,46.5
N759929: length 3.2
  TOP w0.15: U1.52 10.07,37.07 9.8,36.8 Y4.1 C521.1 9.8,34.5
N760199: length 3.8
  TOP w0.15: U1.51 9.57,37.07 9.12,36.62 8.77,36.62 8.3,36.15 Y4.2 8.3,35.8 8.3,35.8 8.3,35.03 8.3,35.03 C511.1 8.3,34.5
N760665: length 1.4
  TOP w0.15: v1(7.17,45.45) 7.2,45.45 7.39,45.26 U1.34
  BOTTOM w0.15: v1(7.17,45.45) 6.59,45.45 R341.2
N760769: length 3.9
  TOP w0.3: 5.7,42.1 v1(5.7,42.05) 5.91,42.26 U1.40
  BOTTOM w0.3: L401.1 4.61,42.35 4.91,42.05 v1(5.7,42.05)
N760773: length 3.3
  TOP w0.3: U1.41 6.71,41.76 v1(6.3,41.35)
  BOTTOM w0.3: v1(6.3,41.35) 6.61,41.66 L401.2
N760777: length 1.1
  TOP w0.15: 12.57,47.32 12.63,47.38 C241.1
  TOP w0.3: U1.24 12.57,47.32
N760781: length 1.6
  TOP w0.3: C491.1 8.03,37.68 8.1,37.61 U1.49
N760789: length 3.6
  TOP w0.3: U1.43 7.21,40.76 6.4,39.95 v1(6.25,39.95)
  BOTTOM w0.3: v1(6.25,39.95) 6.54,39.66 L431.1
N760837: length 19.2
  TOP w0.3: v1(17.7,41.9) 17.7,41.95 17.39,42.26 U1.9 ; v1(11.7,35.8) C561.1 12.4,36.35 12.07,36.68 U1.56
  LAYER3 w0.5: v1(11.7,35.8) 11.7,37.1 12.9,38.3 15.6,38.3 17.7,40.4 v1(17.7,41.9)
  BOTTOM w0.3: v1(11.7,35.8) 11.33,36.17 11.33,36.67 10.17,37.83 C432.2 9.31,37.86 L431.2
N761005: length 6.2
  TOP w0.3: U1.38 5.51,43.26 5.2,42.95 2.34,42.95 L381.1
N761145: length 3.4
  TOP w0.3: A1.1 7.07,56.48 7.25,56.3 8.98,56.3 ANT3.1 9.04,55.51 ANT1.2
N761299: length 0.7
  TOP w0.3: FL1.1 C311.2
N761303: length 0.7
  TOP w0.3: J1.2 9.07,50.16 FL1.3
N761307: length 1.8
  TOP w0.3: J1.1 9.05,53.79 ANT2.2 9.03,53.84 ANT1.1
N764692: length 0.9
  BOTTOM w0.15: U3.7 13.37,52.98 R532.1
N764700: length 0.9
  BOTTOM w0.15: R533.1 U3.3
N804286:
  vias: v1(7.8,10.6) v1(7.85,9.95) v1(8.4,7.6) v1(8.45,10.6) v1(8.5,9.95) v1(8.45,6.95) v1(9.05,7.6) v1(9.1,6.9)
N881760: length 0.6
  TOP w0.15: R537.1 3.92,14.59 U4.7
N881768: length 0.6
  TOP w0.15: U4.3 4.42,11.02 R538.1
N913675: length 4.3
  TOP w0.15: R553.1 19.79,3.67 SW3.1 20.33,5.19 20.33,6.98 19.81,7.5 SW3.2
N916681: length 1.1
  BOTTOM w0.15: Q1.3 19.04,9.47 R548.1 19.04,10.06 R550.2
N924850: length 0.6
  BOTTOM w0.15: Q1.1 19.21,8.29 R552.2

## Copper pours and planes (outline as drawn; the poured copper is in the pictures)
GND on TOP: 3,0.5 3,2.7 1.4,2.7 1.4,3.8 0.5,3.8 0.5,58.5 21.5,58.5 21.5,2.7 19,2.7 19,0.5 15.4,0.5 15.4,6.6 6.6,6.6 6.6,0.5 ; 16 cut-outs
GND on BOTTOM: 3,0.5 3,2.7 1.4,2.7 1.4,3.7 0.5,3.7 0.5,58.5 21.5,58.5 21.5,2.7 19,2.7 19,0.5 15.4,0.5 15.4,6.6 6.6,6.6 6.6,0.5 ; 4 cut-outs
GND on LAYER2: 0.74,5.98 0.85,6.03 0.97,6.05 0.99,6.05 1.01,6.06 1.35,6.39 1.37,6.42 1.37,6.44 1.37,6.51 1.35,6.56 1.3,6.58 1.26,6.58 0.89,6.59 0.71,6.93 0.71,6.95 0.7,6.98 0.61,7.07 0.57,7.07 0.55,7.07 0.51,7.04 0.5,7 0.5,58.5 21.5,58.5 21.5,2.7 19,2.7 19,0.5 15.4,0.5 15.4,6.6 6.6,6.6 6.6,0.5 3,0.5 3,2.7 1.5,2.7 1.5,3.7 1.2,3.7 0.7,4.2 0.7,5.4 0.5,5.4 0.5,6.1 0.51,6.06 0.54,6.04 0.68,5.97 0.72,5.97
VDD on BOTTOM: 18.36,10.5 19.7,10.5 19.7,13.17 14.39,13.17 14.39,12.41 18.36,12.41
VDD on LAYER3: 3,0.5 3,2.7 0.5,2.7 0.5,58.5 21.5,58.5 21.5,2.7 19,2.7 19,0.5 15.4,0.5 15.4,6.6 6.6,6.6 6.6,0.5
VDD_IN on BOTTOM: 10.4,13.16 10.4,10.42 12.51,10.42 12.51,9.38 13.55,9.38 13.54,10.23 12.98,10.23 12.98,12.36 14.18,12.36 14.18,13.16
VDDR on TOP: 4,21.6 4,23.2 4.8,24 5.5,24 5.5,21.6
VDDR on LAYER3: 4,22.8 4,22 10.34,15.66 10.34,14.96 10.58,14.72 12.35,14.72 12.72,15.09 12.72,15.48 5.1,23.1 4.3,23.1
VDDS on LAYER3: 4.8,25.6 4.3,25.6 2.9,24.2 2.9,19.7 7.89,14.71 9.2,14.71 9.7,15.2 9.7,16.1 3.8,22 3.8,23.4 5.1,24.7 5.1,25.3
N804286 on TOP: 9.9,7.92 9.9,6.61 8.05,6.61 8.05,7.92
N804286 on BOTTOM: 7.5,11.41 7.5,9.57 9.9,9.57 9.9,11.41
N804286 on LAYER3: 7.47,10.92 7.47,6.68 9.33,6.68 9.33,8.68 8.82,9.18 8.82,10.92

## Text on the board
Package Geometry/Pastemask Bottom: PASTE BOTTOM
Ref Des/Silkscreen Bottom: MultiFi GATEWAY | REV:0.5 | Model: 2650Gateway | TP3
User.Comments: SOLDERMASK BOTTOM | SOLDERMASK TOP
Package Geometry/Pastemask Top: PASTE TOP
Ref Des/Silkscreen Top: CC3200 Reset | CC3200 UART Load
XSECTION_CHART: L1: TOP CONDUCTOR - COPPER 0.035 MM | *  DIELECTRIC - FR-4 0.175 MM | L2: L2 PLANE - COPPER 0.035 MM | *  DIELECTRIC - FR-4 1.01 MM | L3: L3 PLANE - COPPER 0.035 MM | L4: BOTTOM CONDUCTOR - COPPER 0.035 MM | L5: CARBON PRINT | DESIGN CROSS SECTION CHART | ___________________________ | TOTAL THICKNESS 1.5 MM
BODY_CENTER: FIGURE | SIZE | 0.199898 | 0.999998 | DRILL CHART: TOP to BOTTOM | ALL UNITS ARE IN MILLIMETERS | PLATED | NON-PLATED | QTY | 40 | 294 | 6
